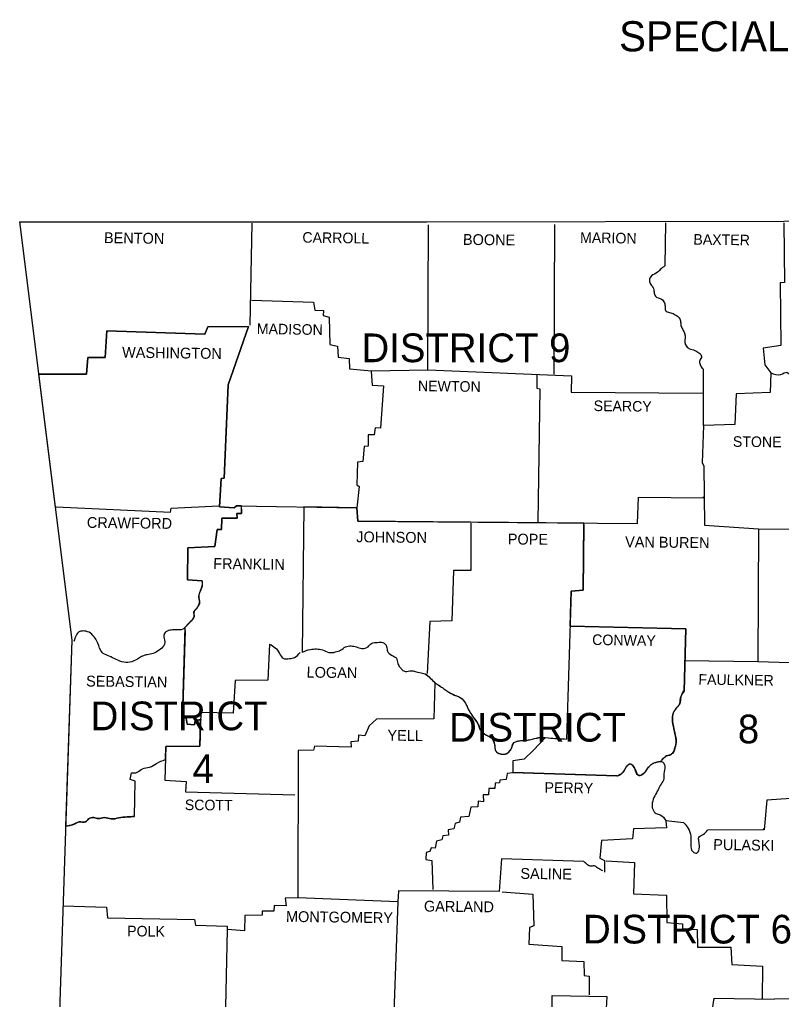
# Model space of a CAD drawing. Extents: x -35254 to 17396, y -8913 to 11592.
# Drawn here: x 11395 to 14355, y 6952 to 10759 of the extents above; entities that cross this region are included whole.
import ezdxf

# ---------------------------------------------------------------- set-up
doc = ezdxf.new("R2010")
doc.units = 0
for name, color, linetype in [('1', 7, 'Continuous'), ('2', 7, 'Continuous'), ('3', 7, 'Continuous'), ('R_Border', 7, 'Continuous'), ('S_MISC_BOUNDARY', 7, 'Continuous')]:
    doc.layers.add(name, color=color, linetype=linetype)

msp = doc.modelspace()

# ---------------------------------------------------------------- linework, layer by layer
at = {"layer": '1'}
for points in [[(11394.6, 9973.9), (12976.6, 9973), (14365, 9975.9), (16002.9, 10001.3), (16762.1, 10019)], [(11394.6, 9973.9), (11597.1, 8347.8), (11509, 5693.4)], [(12297.6, 9968.1), (12288.8, 9571.8)], [(12295.7, 9668.7), (12536.4, 9660.9), (12542.2, 9629.5), (12575.5, 9628.6), (12574.5, 9609), (12598, 9603.1), (12600, 9496.5), (12630.3, 9489.6), (12632.2, 9447.6), (12675.3, 9441.7), (12677.3, 9402.6), (12762.4, 9393.8), (12981.5, 9398.6), (12983.5, 9961.2)], [(13473.7, 9963.2), (13470.7, 9382)], [(13904.2, 9970), (13902.2, 9802.7)], [(14365, 9970), (14367, 9737.2), (14350.3, 9736.2), (14353.3, 9492.6), (14284.8, 9482.8), (14290.6, 9417.2), (14314.1, 9386.9), (14312.2, 9309.6), (14179.1, 9304.7), (14174.2, 9185.3), (14052.9, 9181.4), (14047, 9036.6), (14053.9, 9024.9), (14056.8, 8794), (14266.2, 8780.3), (14263.2, 8264.7), (14429.6, 8259.8), (14429.6, 7735.4), (14298.5, 7725.6), (14288.7, 7610.1), (14068.5, 7609.1)], [(11471.9, 9382), (11654.8, 9381), (11659.7, 9445.6), (11727.2, 9445.6), (11733.1, 9550.3), (12114.7, 9536.6), (12126.4, 9565.9), (12283.9, 9566.9), (12204.7, 9339.9), (12189, 8976.9), (12177.3, 8976), (12171.4, 8866.4), (12229.1, 8861.5), (12237.9, 8870.3), (12704.6, 8861.5), (12709.5, 8809.6)], [(12760.4, 9391.8), (12764.3, 9339), (12809.3, 9336), (12797.6, 9171.7), (12777, 9172.6), (12773.1, 9146.2), (12749.7, 9146.2), (12748.7, 9101.2), (12734, 9100.2), (12729.1, 9042.5), (12707.6, 9039.6), (12704.6, 8951.5), (12714.4, 8944.7), (12704.6, 8861.5)], [(12981.5, 9398.6), (13539.2, 9375.2), (13538.3, 9311.6), (14050, 9307.7)], [(13405.2, 9378.1), (13404.2, 9327.2), (13416.9, 9324.3), (13409.1, 8807.7)], [(14052.9, 9181.4), (14051.9, 9401.6)], [(12709.5, 8809.6), (13795.6, 8800.8), (13800.5, 8903.6), (14052.9, 8900.6)], [(14050, 8901.6), (14052.9, 8904.5)], [(11536.4, 8865.4), (11981.6, 8844.9), (11983.6, 8860.5), (12169.5, 8869.3)], [(12257.5, 8857.6), (12257.5, 8840), (12238.9, 8840), (12239.9, 8822.4), (12180.2, 8821.4), (12179.2, 8777.4), (12162.6, 8777.4), (12153.8, 8711.8), (12048.1, 8706.9), (12047.2, 8582.7), (12103.9, 8578.7)], [(12499.2, 8865.4), (12492.3, 8300.9)], [(13148.8, 8801.8), (13147.9, 8618.9), (13080.4, 8617.9), (13074.5, 8423.2), (12988.4, 8420.2), (12978.6, 8218.7)], [(13587.2, 8796.9), (13585.2, 8542.5), (13538.3, 8538.6), (13519.7, 7963.3)], [(14266.2, 8780.3), (14769.1, 8777.4), (14812.1, 8797.9), (14809.2, 8415.3), (14779.8, 8402.6), (14753.4, 8380.1), (14744.6, 8371.3), (14743.6, 8261.7), (14423.7, 8261.7)], [(12037.4, 8385), (12027.6, 8048.4), (12042.3, 8044.5), (12045.2, 8021), (12074.6, 8019.1), (12077.5, 8035.7), (12101, 8039.6)], [(13536.3, 8402.6), (13983.4, 8391.9), (13977.6, 8150.2)], [(12366.1, 8332.2), (12359.3, 8192.3), (12232.1, 8191.3), (12225.2, 8064.1), (12099, 8067), (12095.1, 7935.9), (11963, 7934.9), (11959.1, 7803.8), (12042.3, 7798.9), (12039.3, 7758.8), (12464, 7747.1)], [(13978.5, 8268.6), (14263.2, 8264.7)], [(13008.9, 8182.5), (13005, 8041.6), (12781.9, 8040.6), (12752.6, 8015.2), (12736, 7976), (12711.5, 7978), (12710.5, 7955.5), (12682.1, 7952.6), (12683.1, 7932), (12541.3, 7935.9), (12536.4, 7920.3), (12477.7, 7918.3), (12475.7, 7345.9), (12426.8, 7345), (12430.7, 7315.6), (12383.7, 7316.6), (12382.8, 7295.1), (12336.8, 7295.1), (12337.7, 7279.4), (12269.3, 7277.5), (12268.3, 7217.8), (12201.7, 7223.6), (12191, 6742.3)], [(13428.7, 7959.4), (13393.4, 7921.2), (13355.3, 7885), (13311.3, 7878.2), (13311.3, 7832.2), (13289.7, 7829.3), (13285.8, 7805.8), (13261.4, 7803.8), (13259.4, 7793.1), (13242.8, 7792.1), (13241.8, 7771.6), (13218.3, 7770.6), (13216.4, 7747.1), (13196.8, 7747.1), (13197.8, 7719.7), (13176.2, 7721.7), (13175.3, 7700.1), (13148.8, 7698.2), (13141, 7662.9), (13107.8, 7660), (13104.8, 7640.4), (13087.2, 7635.6), (13082.3, 7615), (13059.8, 7610.1), (13061.8, 7589.6), (13039.3, 7587.6), (13035.3, 7572), (13014.8, 7566.1), (13009.9, 7539.7), (12994.3, 7540.6), (12989.4, 7527), (12974.7, 7522.1), (12973.7, 7495.6), (12996.2, 7491.7), (13000.1, 7378.2)], [(11840.7, 7662), (11843.6, 7799.9), (11824.1, 7805.8), (11830, 7832.2)], [(13715.3, 7820.5), (13312.2, 7833.2)], [(13976.6, 7637.5), (13906.1, 7645.3), (13909.1, 7618.9), (13780.9, 7614), (13777, 7575.9), (13656.6, 7569), (13649.8, 7500.5), (13667.4, 7491.7), (13667.4, 7446.7)], [(14283.8, 7611.1), (14288.7, 7616)], [(13587.2, 7487.8), (13267.2, 7497.6), (13258.4, 7371.4), (12867.1, 7373.3), (12865.1, 7331.3)], [(13674.2, 7490.7), (13783.8, 7483.9), (13779.9, 7361.6), (13908.1, 7356.7), (13910, 7250.1), (13970.7, 7245.2), (13970.7, 7226.6), (14027.5, 7222.7), (14029.4, 7154.2), (14158.6, 7154.2), (14162.5, 7086.7), (14281.8, 7080.8), (14280.9, 6953.6)], [(13270.2, 7369.4), (13388.6, 7360.6), (13392.5, 7237.3), (13375.8, 7231.5), (13373.9, 7165.9), (13502, 7157.1), (13502, 7103.3), (13587.2, 7098.4), (13588.1, 7044.6), (13608.7, 7041.7), (13607.7, 6969.3)], [(11562.8, 7315.6), (11732.1, 7309.7), (11736, 7268.7), (12074.6, 7261.8), (12078.5, 7240.3), (12201.7, 7236.4), (12200.8, 7217.8)], [(12865.1, 7331.3), (12475.7, 7345.9)], [(12865.1, 7331.3), (12842.6, 6721.7)], [(15448.1, 7066.1), (15078.3, 7075.9), (15076.3, 6955.6), (14327.8, 6952.6)], [(12849.5, 6802.9), (13409.1, 6795.1), (13419.9, 6888.1), (13463.9, 6888.1), (13464.9, 6966.3), (13676.2, 6963.4), (13674.2, 6916.4), (13729, 6912.5), (13729, 6826.4), (13764.3, 6823.5)], [(13764.3, 6823.5), (13819.1, 6831.3), (13823, 6864.6), (13855.3, 6870.4), (13857.2, 6890), (14085.2, 6896.9), (14094, 6956.5), (14327.8, 6952.6)]]:
    msp.add_lwpolyline(points, dxfattribs=at)
for points in [[(13902.2, 9802.7), (13884.6, 9788), (13869, 9774.4), (13845.5, 9757.7), (13842.5, 9742.1), (13850.4, 9726.4), (13858.2, 9713.7), (13861.1, 9696.1), (13868, 9681.4), (13884.6, 9675.5), (13898.3, 9662.8), (13903.2, 9645.2), (13905.2, 9628.6), (13920.8, 9620.7), (13938.4, 9614.9), (13955.1, 9603.1), (13962.9, 9588.5), (13964.8, 9569.9), (13971.7, 9555.2), (13979.5, 9537.6), (13981.5, 9522.9), (13979.5, 9508.2), (13983.4, 9494.5), (13996.1, 9480.8), (14018.6, 9474), (14034.3, 9464.2), (14045.1, 9450.5), (14038.2, 9433.9), (14039.2, 9419.2), (14048, 9401.6)], [(14314.1, 9386.9), (14353.3, 9380.1), (14376.7, 9388.9), (14393.4, 9363.4), (14402.2, 9343.9), (14416.9, 9315.5), (14440.3, 9306.7), (14458, 9291), (14458, 9274.4), (14442.3, 9258.7), (14430.6, 9243.1), (14434.5, 9224.5), (14438.4, 9199), (14438.4, 9174.6), (14432.5, 9152.1), (14427.6, 9131.5), (14432.5, 9113.9), (14451.1, 9116.9), (14470.7, 9131.5), (14491.2, 9131.5), (14510.8, 9120.8), (14531.3, 9102.2), (14551.9, 9106.1), (14568.5, 9111), (14592, 9117.8), (14608.6, 9109), (14623.3, 9097.3), (14640.9, 9078.7), (14657.5, 9067), (14679.1, 9056.2), (14705.5, 9049.4), (14729.9, 9032.7), (14733.9, 9004.3), (14732.9, 8979.9), (14730.9, 8949.6), (14729, 8916.3), (14731.9, 8884), (14742.7, 8862.5), (14756.4, 8837), (14760.3, 8813.6), (14759.3, 8776.4)], [(12103.9, 8578.7), (12103.9, 8558.2), (12096.1, 8536.7), (12091.2, 8518.1), (12094.1, 8493.6), (12085.3, 8474), (12072.6, 8458.4), (12072.6, 8438.8), (12057.9, 8418.3), (12042.3, 8402.6), (12028.6, 8389.9), (12004.1, 8387.9), (11983.6, 8387), (11963, 8380.1), (11955.2, 8365.4), (11959.1, 8342.9), (11951.3, 8321.4), (11930.7, 8304.8), (11908.2, 8294), (11884.7, 8290.1), (11852.5, 8274.5), (11823.1, 8261.7), (11791.8, 8263.7), (11762.4, 8276.4), (11736, 8288.2), (11715.5, 8299.9), (11698.8, 8336.1), (11688.1, 8355.7), (11669.5, 8375.2), (11647, 8383.1), (11628.4, 8381.1), (11605.9, 8342.9)], [(12492.3, 8300.9), (12524.6, 8311.6), (12548.1, 8313.6), (12571.6, 8309.7), (12596, 8299.9), (12622.5, 8301.8), (12642, 8308.7), (12661.6, 8321.4), (12683.1, 8325.3), (12703.7, 8321.4), (12725.2, 8315.5), (12748.7, 8322.4), (12762.4, 8335.1), (12785.9, 8339), (12806.4, 8339), (12821.1, 8322.4), (12824, 8304.8), (12842.6, 8288.2), (12859.2, 8277.4), (12864.1, 8256.8), (12872.9, 8242.2), (12881.7, 8232.4), (12894.5, 8226.5), (12916, 8228.5), (12949.2, 8221.6), (12970.8, 8216.7), (12990.3, 8200.1), (13008.9, 8182.5)], [(12366.1, 8332.2), (12387.6, 8318.5), (12404.3, 8296), (12419, 8277.4), (12443.4, 8276.4), (12463, 8280.3), (12485.5, 8299.9)], [(13008.9, 8182.5), (13043.2, 8159), (13075.5, 8138.5), (13108.7, 8123.8), (13127.3, 8102.3), (13144, 8069), (13157.7, 8048.4), (13175.3, 8023), (13188, 7994.6), (13208.5, 7979), (13230.1, 7965.3), (13240.8, 7940.8), (13245.7, 7916.4), (13269.2, 7904.6), (13291.7, 7909.5), (13304.4, 7924.2), (13316.2, 7949.6), (13342.6, 7957.4), (13376.8, 7960.4), (13415.9, 7969.2), (13459, 7967.2), (13519.7, 7963.3)], [(13977.6, 8150.2), (13964.8, 8127.7), (13959, 8098.3), (13943.3, 8079.7), (13933.5, 8058.2), (13932.5, 8029.9), (13937.4, 8004.4), (13942.3, 7980), (13946.2, 7957.4), (13941.4, 7929.1), (13928.6, 7904.6), (13909.1, 7897.8), (13890.5, 7881.1)], [(11830, 7832.2), (11851.5, 7834.2), (11872, 7847.9), (11899.4, 7853.7), (11926.8, 7868.4), (11961.1, 7884.1)], [(13715.3, 7820.5), (13739.8, 7834.2), (13752.5, 7854.7), (13768.2, 7867.4), (13783.8, 7849.8), (13797.5, 7824.4), (13812.2, 7824.4), (13830.8, 7842), (13842.5, 7857.7), (13857.2, 7869.4), (13872.9, 7874.3), (13889.5, 7876.2), (13902.2, 7857.7), (13898.3, 7828.3), (13898.3, 7808.7), (13887.5, 7788.2), (13875.8, 7766.7), (13863.1, 7742.2), (13853.3, 7715.8), (13855.3, 7690.3), (13869, 7673.7), (13884.6, 7668.8), (13906.1, 7647.3)], [(11840.7, 7662), (11812.3, 7661), (11780.1, 7657.1), (11750.7, 7653.2), (11724.3, 7658.1), (11699.8, 7654.1), (11683.2, 7658.1), (11662.6, 7653.2), (11650.9, 7641.4), (11626.4, 7641.4), (11608.8, 7633.6), (11580.5, 7626.7)], [(13976.6, 7637.5), (13993.2, 7616), (14003, 7586.6), (14003, 7553.4), (14010.8, 7526), (14026.5, 7520.1), (14036.3, 7543.6), (14034.3, 7567.1), (14034.3, 7580.8), (14050.9, 7592.5), (14068.5, 7609.1)], [(13660.6, 7451.6), (13642, 7461.4), (13627.3, 7470.2), (13611.6, 7469.2), (13598.9, 7477.1), (13587.2, 7487.8)]]:
    msp.add_spline(points, degree=3, dxfattribs=at)
at = {"layer": 'S_MISC_BOUNDARY'}
for points in [[(12103.9, 8578.7), (12047.2, 8582.7), (12048.1, 8706.9), (12153.8, 8711.8), (12162.6, 8777.4), (12179.2, 8777.4), (12180.2, 8821.4), (12239.9, 8822.4), (12238.9, 8840), (12257.5, 8840), (12257.5, 8869.9), (12237.9, 8870.3), (12229.1, 8861.5), (12171.4, 8866.4), (12177.3, 8976), (12189, 8976.9), (12204.7, 9339.9), (12283.9, 9566.9), (12126.4, 9565.9), (12114.7, 9536.6), (11733.1, 9550.3), (11727.2, 9445.6), (11659.7, 9445.6), (11654.8, 9381), (11468.3, 9382)], [(11468.3, 9382), (11597.1, 8347.8), (11573.1, 7625.5)], [(13587.2, 8802.6), (12709.5, 8809.7), (12704.6, 8861.5), (12499.2, 8865.4), (12492.3, 8300.9)], [(13977.6, 8150.2), (13983.4, 8391.9), (13533.9, 8402.7), (13538.3, 8538.7), (13585.2, 8542.6), (13587.2, 8802.6)], [(11961.1, 7884.1), (11963, 7934.9), (12095.1, 7935.9), (12098.2, 8039.2), (12077.5, 8035.7), (12074.6, 8019.1), (12045.2, 8021), (12042.3, 8044.5), (12027.6, 8048.4), (12037.7, 8397.6)], [(13437.1, 7968.5), (13393.4, 7921.3), (13355.3, 7885.1), (13311.3, 7878.2), (13311.3, 7833.3), (13715.3, 7820.5)], [(11840.7, 7662), (11843.6, 7799.9), (11824.1, 7805.8), (11830, 7832.2)]]:
    msp.add_lwpolyline(points, dxfattribs=at)
for points in [[(12089, 8480.5), (12090.5, 8483.6), (12092.6, 8488.5), (12093.4, 8491), (12094.1, 8493.6), (12094.4, 8496.6), (12094.2, 8499.7), (12092.7, 8505.9), (12091.2, 8512), (12091.2, 8518.1), (12092.2, 8522.8), (12093.3, 8527.4), (12094.6, 8532.1), (12096.1, 8536.7), (12098, 8542.1), (12100.1, 8547.4), (12102.1, 8552.8), (12103.9, 8558.2), (12105.2, 8568.4), (12104.8, 8573.6), (12103.9, 8578.7)], [(12037.7, 8397.6), (12039.1, 8399.1), (12042.3, 8402.6), (12046.1, 8406.6), (12050.1, 8410.5), (12054, 8414.3), (12057.9, 8418.3), (12062.1, 8423), (12065.9, 8428.1), (12069.4, 8433.4), (12071, 8436.1), (12072.6, 8438.8), (12073.5, 8443.5), (12072.7, 8448.6), (12071.8, 8453.7), (12071.8, 8456.1), (12072.6, 8458.4), (12073.2, 8459.5), (12073.9, 8460.6), (12075.4, 8462.5), (12078.8, 8466.2), (12082.3, 8469.9), (12085.3, 8474), (12087.2, 8477.2), (12089, 8480.5)], [(12492.3, 8300.9), (12524.6, 8311.7), (12548.1, 8313.6), (12571.6, 8309.7), (12596, 8299.9), (12622.5, 8301.9), (12642, 8308.7), (12661.6, 8321.5), (12683.1, 8325.4), (12703.7, 8321.5), (12725.2, 8315.6), (12748.7, 8322.4), (12762.4, 8335.2), (12785.9, 8339.1), (12806.4, 8339.1), (12821.1, 8322.4), (12824, 8304.8), (12842.6, 8288.2), (12859.2, 8277.4), (12864.1, 8256.9), (12872.9, 8242.2), (12881.7, 8232.4), (12894.5, 8226.5), (12916, 8228.5), (12949.2, 8221.7), (12970.8, 8216.8), (12990.3, 8200.1), (13008.9, 8182.5)], [(13008.9, 8182.5), (13043.2, 8159), (13059.2, 8148.5), (13067.3, 8143.5), (13075.5, 8138.5), (13083.6, 8134.5), (13092.1, 8131.4), (13100.6, 8128.2), (13104.8, 8126.2), (13108.7, 8123.8), (13119.2, 8114.1), (13127.3, 8102.3), (13131.6, 8094), (13135.4, 8085.5), (13139.4, 8077.1), (13144, 8069), (13152.9, 8055.5)], [(13937.3, 8005.3), (13932.5, 8029.9), (13931.7, 8036.9), (13931.6, 8044), (13932.2, 8051.2), (13932.8, 8054.7), (13933.5, 8058.3), (13937.5, 8069.4), (13940.3, 8074.6), (13943.3, 8079.8), (13947, 8084.6), (13951.4, 8089), (13955.6, 8093.4), (13959, 8098.4), (13960.3, 8101.8), (13961.2, 8105.3), (13962, 8112.7), (13962.8, 8120.3), (13964.8, 8127.7), (13966.3, 8131.2), (13967.9, 8135.3), (13971.3, 8143.4), (13972.8, 8146.4), (13973.6, 8147.9), (13974.6, 8149.4), (13976.2, 8150.6), (13977.6, 8150.2)], [(13152.9, 8055.5), (13157.7, 8048.5), (13175.3, 8023), (13178.7, 8016.1), (13181.1, 8008.5), (13183.7, 8001.1), (13185.6, 7997.7), (13188, 7994.7), (13197.9, 7986.3), (13208.5, 7979), (13211.2, 7977.3), (13213.9, 7975.7), (13219.5, 7972.7), (13227.6, 7967.5), (13228.8, 7966.4), (13230.1, 7965.3), (13234.2, 7959.9), (13236.9, 7953.8), (13238.9, 7947.3), (13240.8, 7940.9), (13241.6, 7937.9), (13241.9, 7934.8), (13242.1, 7928.6), (13242.9, 7922.4), (13243.9, 7919.3), (13244.7, 7917.9), (13245.7, 7916.4), (13250.8, 7911.3), (13256.6, 7907.9), (13262.9, 7905.8), (13266, 7905.1)], [(13884.9, 7876.5), (13887.7, 7879.4), (13890.1, 7882.7), (13892.6, 7885.9), (13895.6, 7888.6), (13902.3, 7893.3), (13905.7, 7895.6), (13909.1, 7897.8), (13913.8, 7899.8), (13919.1, 7900.7), (13924.2, 7901.9), (13928.6, 7904.7), (13929.9, 7906), (13931, 7907.3), (13933.1, 7910.2), (13936.6, 7916.1), (13939.2, 7922.5), (13941.4, 7929.1), (13942.4, 7932.7), (13943.5, 7936.2), (13945.4, 7943.3), (13946.5, 7950.4), (13946.2, 7957.5), (13945.4, 7963.1), (13944.4, 7968.7), (13942.3, 7980), (13937.4, 8004.4), (13937.3, 8005.3)], [(13266, 7905.1), (13269.2, 7904.7), (13274.8, 7904.3), (13280.6, 7904.9), (13286.3, 7906.5), (13291.7, 7909.5), (13295.6, 7912.9), (13298.8, 7916.5), (13304.4, 7924.2), (13306.1, 7927.3), (13307.3, 7930.6), (13309.2, 7937.6), (13311.6, 7944.3), (13313.5, 7947.2), (13314.7, 7948.5), (13316.2, 7949.7), (13329, 7955.4), (13342.6, 7957.5), (13351.1, 7958.3), (13359.7, 7958.9), (13368.3, 7959.5), (13376.8, 7960.4), (13386.6, 7962.6), (13396.3, 7965.6), (13406.1, 7968.2), (13415.9, 7969.2), (13437.1, 7968.5)], [(11830, 7832.2), (11851.5, 7834.2), (11872, 7847.9), (11899.4, 7853.7), (11926.8, 7868.4), (11961.1, 7884.1)], [(13715.3, 7820.5), (13716.9, 7820.7), (13718.5, 7821), (13721.7, 7822), (13727.9, 7824.9), (13734, 7829.1), (13736.9, 7831.6), (13739.8, 7834.2), (13742, 7836.6), (13743.7, 7839.1), (13746.4, 7844.4), (13749, 7849.7), (13752.5, 7854.8), (13754.4, 7856.9), (13756.3, 7859.2), (13760.4, 7863.7), (13762.2, 7865.4), (13763.3, 7866.2), (13764.4, 7866.9), (13766.3, 7867.6), (13767.3, 7867.6), (13767.7, 7867.6), (13768.2, 7867.5), (13772.3, 7864.9), (13773.4, 7863.8), (13774.4, 7862.7), (13776.2, 7860.4), (13780.1, 7855.1), (13782, 7852.4), (13783.8, 7849.9), (13784.9, 7848.3), (13787.6, 7843.5), (13790.5, 7836.8), (13792.7, 7831.9)], [(13792.7, 7831.9), (13793.4, 7830.3), (13795.3, 7827.2), (13796.3, 7825.8), (13797.5, 7824.4), (13799, 7823.3), (13799.8, 7822.8), (13800.7, 7822.5), (13802.7, 7822), (13804.7, 7822), (13808.8, 7822.7), (13809.7, 7823), (13810.6, 7823.4), (13812.2, 7824.4), (13817.1, 7828.4), (13821.9, 7832.7), (13826.5, 7837.2), (13830.8, 7842), (13833.8, 7845.9), (13836.6, 7849.9), (13839.4, 7853.9), (13842.5, 7857.7), (13849.3, 7864.2), (13853.1, 7867), (13855.1, 7868.3), (13857.2, 7869.4), (13861, 7871.1), (13865, 7872.3), (13868.9, 7873.3), (13872.9, 7874.3), (13876.8, 7875.5), (13880.9, 7876.6), (13884.9, 7876.5)], [(11573.1, 7625.5), (11608.8, 7633.6), (11626.4, 7641.4), (11650.9, 7641.4), (11662.6, 7653.2), (11683.2, 7658.1), (11699.8, 7654.1), (11724.3, 7658.1), (11750.7, 7653.2), (11780.1, 7657.1), (11812.3, 7661), (11840.7, 7662)]]:
    msp.add_spline(points, degree=3, dxfattribs=at)

# ---------------------------------------------------------------- texts
at = {"layer": '2'}
for s, height, rotation, p in [('BENTON', 42.07, 359.2527, (11722.3, 9890.8)), ('CARROLL', 41.09, 359.1481, (12493.3, 9892.7)), ('BOONE', 42.07, 359.4001, (13117.5, 9883.9)), ('MARION', 41.09, 359.1854, (13572.5, 9891.8)), ('BAXTER', 41.09, 359.2559, (14012.8, 9884.9)), ('MADISON', 41.09, 359.0906, (12316.2, 9537.6)), ('WASHINGTON', 42.06, 359.232, (11792.8, 9445.6)), ('NEWTON', 41.09, 359.2717, (12942.4, 9315.5)), ('SEARCY', 41.08, 359.2527, (13625.3, 9238.2)), ('STONE', 41.08, 359.4001, (14166.4, 9099.2)), ('CRAWFORD', 42.06, 359.2771, (11655.8, 8784.2)), ('JOHNSON', 42.07, 359.3514, (12702.7, 8728.4)), ('POPE', 42.07, 359.6155, (13291.7, 8719.6)), ('VAN BUREN', 42.07, 359.3508, (13747.6, 8708.9)), ('FRANKLIN', 42.07, 359.1815, (12147, 8624.7)), ('CONWAY', 41.08, 359.0371, (13619.5, 8329.2)), ('LOGAN', 42.07, 359.3969, (12509.9, 8202.1)), ('SEBASTIAN', 42.06, 359.2816, (11652.9, 8167.8)), ('FAULKNER', 41.09, 359.2486, (14032.3, 8174.7)), ('YELL', 42.07, 359.1987, (12824, 7957.4)), ('PERRY', 41.09, 359.0858, (13434.5, 7754.9)), ('SCOTT', 41.09, 359.4063, (12036.4, 7687.4)), ('PULASKI', 42.07, 359.053, (14090.1, 7532.8)), ('SALINE', 42.07, 359.1491, (13340.6, 7420.3)), ('GARLAND', 42.07, 359.3658, (12965.9, 7293.1)), ('MONTGOMERY', 42.07, 359.2944, (12429.7, 7253)), ('POLK', 41.08, 359.2152, (11812.3, 7197.2))]:
    msp.add_text(s, height=height, rotation=rotation, dxfattribs=at).set_placement(p)
at = {"layer": '3'}
for s, height, p in [('DISTRICT 9', 111.54, (12723.2, 9428)), ('DISTRICT', 111.54, (11670.5, 7997.6)), ('DISTRICT', 111.54, (13063.7, 7953.5)), ('8', 111.5, (14186, 7946.7)), ('4', 111.5, (12066.7, 7792.1)), ('DISTRICT 6', 111.54, (13584.2, 7168.9))]:
    msp.add_text(s, height=height, dxfattribs=at).set_placement(p)
at = {"layer": 'R_Border'}
msp.add_text('SPECIALIZED BRIDGE DECK REHAB. (2021) (S)', height=117.24, dxfattribs=at).set_placement((13724.4, 10635.8))

doc.saveas('drawing.dxf')
